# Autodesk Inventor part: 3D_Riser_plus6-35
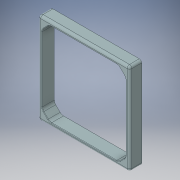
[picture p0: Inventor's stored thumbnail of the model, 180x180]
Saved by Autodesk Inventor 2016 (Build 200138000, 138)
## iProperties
Created: 2016-01
Part Number: 3D_Riser_plus6-35
Material: Generic
Document SubType Name: Modeling
Designer: John
Density: 1 g/cm^3
Appearance: Default
Author: John
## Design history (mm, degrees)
feature "Base1"
sketch "Sketch1"
  geometry: L1 (0, 0)-(180, 0) reference; L2 (185, 5)-(185, 185) reference; L3 (180, 190)-(0, 190) reference; L4 (-5, 185)-(-5, 5) reference; L5 (22.142, 182)-(157.858, 182) reference; L6 (174.071, 169.929)-(164.929, 179.071) reference; L7 (177, 162.858)-(177, 27.142) reference; L8 (164.929, 10.929)-(174.071, 20.071) reference; L9 (157.858, 8)-(22.142, 8) reference; L10 (5.929, 20.071)-(15.071, 10.929) reference; L11 (3, 27.142)-(3, 162.858) reference; L12 (15.071, 179.071)-(5.929, 169.929) reference; C1 r 1.75 at (3, 182) reference; C2 r 1.75 at (177, 8) reference; C3 r 1.75 at (177, 182) reference; C4 r 1.75 at (3, 8) reference; A1 r 5 centre (0, 5) between (-5, 5) and (0, 0) reference; A2 r 5 centre (180, 5) between (180, 0) and (185, 5) reference; A3 r 5 centre (180, 185) between (185, 185) and (180, 190) reference; A4 r 5 centre (0, 185) between (0, 190) and (-5, 185) reference; A5 r 10 centre (157.858, 172) between (164.929, 179.071) and (157.858, 182) reference; A6 r 10 centre (167, 162.858) between (177, 162.858) and (174.071, 169.929) reference; A7 r 10 centre (167, 27.142) between (174.071, 20.071) and (177, 27.142) reference; A8 r 10 centre (157.858, 18) between (157.858, 8) and (164.929, 10.929) reference; A9 r 10 centre (22.142, 18) between (15.071, 10.929) and (22.142, 8) reference; A10 r 10 centre (13, 27.142) between (3, 27.142) and (5.929, 20.071) reference; A11 r 10 centre (13, 162.858) between (5.929, 169.929) and (3, 162.858) reference; A12 r 10 centre (22.142, 172) between (22.142, 182) and (15.071, 179.071) reference; 1 further point
extrude "Extrusion1" join sketch "Sketch1" distance "d0" = 6.35; taper "d1" = 0 deg
sketch "Sketch2"
  geometry: L1 (164.929, 179.071)-(174.071, 169.929) reference; L2 (177, 162.858)-(177, 27.142) reference; L3 (174.071, 20.071)-(164.929, 10.929) reference; L4 (157.858, 8)-(22.142, 8) reference; L5 (15.071, 10.929)-(5.929, 20.071) reference; L6 (3, 27.142)-(3, 162.858) reference; L7 (5.929, 169.929)-(15.071, 179.071) reference; L8 (22.142, 182)-(157.858, 182) reference; L9 (0, 0)-(180, 0) reference; L10 (185, 5)-(185, 185) reference; L11 (180, 190)-(0, 190) reference; L12 (-5, 185)-(-5, 5) reference; C1 r 1.75 at (3, 8) reference; C2 r 1.75 at (177, 182) reference; C3 r 1.75 at (177, 8) reference; C4 r 1.75 at (3, 182) reference; A1 r 10 centre (157.858, 172) between (164.929, 179.071) and (157.858, 182) reference; A2 r 10 centre (167, 162.858) between (177, 162.858) and (174.071, 169.929) reference; A3 r 10 centre (167, 27.142) between (174.071, 20.071) and (177, 27.142) reference; A4 r 10 centre (157.858, 18) between (157.858, 8) and (164.929, 10.929) reference; A5 r 10 centre (22.142, 18) between (15.071, 10.929) and (22.142, 8) reference; A6 r 10 centre (13, 27.142) between (3, 27.142) and (5.929, 20.071) reference; A7 r 10 centre (13, 162.858) between (5.929, 169.929) and (3, 162.858) reference; A8 r 10 centre (22.142, 172) between (22.142, 182) and (15.071, 179.071) reference; A9 r 5 centre (0, 5) between (-5, 5) and (0, 0) reference; A10 r 5 centre (180, 5) between (180, 0) and (185, 5) reference; A11 r 5 centre (180, 185) between (185, 185) and (180, 190) reference; A12 r 5 centre (0, 185) between (0, 190) and (-5, 185) reference; 1 further point
extrude "Extrusion2" join sketch "Sketch2" distance "d2" = 6.35; taper "d3" = 0 deg
thicken "Thicken1" dims "d4" = 0.5, "d5" = 0.5
thicken "Thicken2" dims "d6" = 0.5, "d7" = 0.5
thicken "Thicken3" dims "d8" = 0.5, "d9" = 0.5
thicken "Thicken4" dims "d10" = 0.5, "d11" = 0.5
body "Solid1"
node "Projected Loop1"
node "Projected Loop2"
